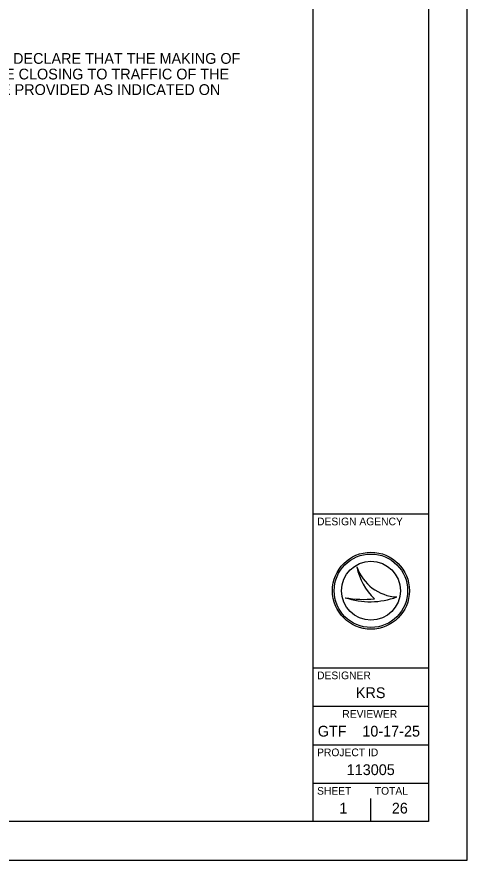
# Model space of a CAD drawing. Extents: x 0 to 34, y 0 to 22.
# Drawn here: x 28.15 to 34, y 0 to 10.96 of the extents above; entities that cross this region are included whole.
import ezdxf

# ---------------------------------------------------------------- set-up
doc = ezdxf.new("R2010")
doc.units = 0
for name, color, linetype in [('Default', 7, 'Continuous'), ('SH_Border', 7, 'Continuous'), ('SH_Cut_Line', 7, 'Continuous'), ('SH_Data', 7, 'Continuous')]:
    doc.layers.add(name, color=color, linetype=linetype)

msp = doc.modelspace()

# ---------------------------------------------------------------- linework, layer by layer
at = {"layer": 'SH_Border'}
for p, q in [((32, 0.5), (32, 21.5)), ((32, 4.5), (33.5, 4.5)), ((32, 2.5), (33.5, 2.5)), ((32, 2), (33.5, 2)), ((32, 1.5), (33.5, 1.5)), ((32, 1), (33.5, 1))]:
    msp.add_line(p, q, dxfattribs=at)
msp.add_lwpolyline([(1.5, 21.5), (33.5, 21.5), (33.5, 0.5), (1.5, 0.5)], close=True, dxfattribs=at)
at = {"layer": 'SH_Cut_Line'}
msp.add_lwpolyline([(0, 0), (34, 0), (34, 22), (0, 22)], close=True, dxfattribs=at)
at = {"layer": 'SH_Data'}
for p, q in [((32.567, 3.81), (32.567, 3.81)), ((32.417, 3.41), (32.417, 3.41)), ((32.75, 3.5), (32.75, 3.5)), ((33.087, 3.419), (33.087, 3.419)), ((32.75, 0.5), (32.75, 0.8)), ((32.375, 0.675), (32.375, 0.675))]:
    msp.add_line(p, q, dxfattribs=at)
for radius in [0.5, 0.477, 0.477, 0.382]:
    msp.add_circle((32.75, 3.5), radius, dxfattribs=at)
for centre, radius, start, end in [((33.116, 3.998), 0.58, 198.9257, 198.9319), ((33.347, 3.97), 0.796, 191.6379, 191.6421), ((33.116, 3.998), 0.58, 198.9319, 267.1657), ((33.347, 3.97), 0.796, 191.6421, 226.0947), ((32.739, 4.37), 1.013, 251.4576, 290.0832), ((32.648, 4.654), 1.266, 259.4964, 259.4995), ((32.739, 4.37), 1.013, 251.4527, 251.4576), ((32.648, 4.654), 1.266, 259.4995, 276.6672)]:
    msp.add_arc(centre, radius, start, end, dxfattribs=at)

# ---------------------------------------------------------------- texts
at = {"layer": 'Default'}
for s, p in [('I HEREBY APPROVE THESE PLANS AND DECLARE THAT THE MAKING OF', (24.427, 10.345)), ('THIS IMPROVEMENT WILL REQUIRE THE CLOSING TO TRAFFIC OF THE', (24.427, 10.142)), ('HIGHWAY AND THAT DETOURS WILL BE PROVIDED AS INDICATED ON', (24.427, 9.94))]:
    msp.add_text(s, height=0.14, dxfattribs=at).set_placement(p)
at = {"layer": 'SH_Data'}
for s, height, p in [('DESIGN AGENCY', 0.1, (32.05, 4.35)), ('DESIGNER', 0.1, (32.05, 2.35)), ('KRS', 0.14, (32.554, 2.105)), ('REVIEWER', 0.1, (32.378, 1.85)), ('GTF', 0.14, (32.059, 1.605)), ('10-17-25', 0.14, (32.638, 1.605)), ('PROJECT ID', 0.1, (32.05, 1.35)), ('113005', 0.14, (32.435, 1.105)), ('SHEET', 0.1, (32.05, 0.85)), ('TOTAL', 0.1, (32.8, 0.85)), ('1', 0.14, (32.339, 0.605)), ('26', 0.14, (33.021, 0.605))]:
    msp.add_text(s, height=height, dxfattribs=at).set_placement(p)

doc.saveas('drawing.dxf')
